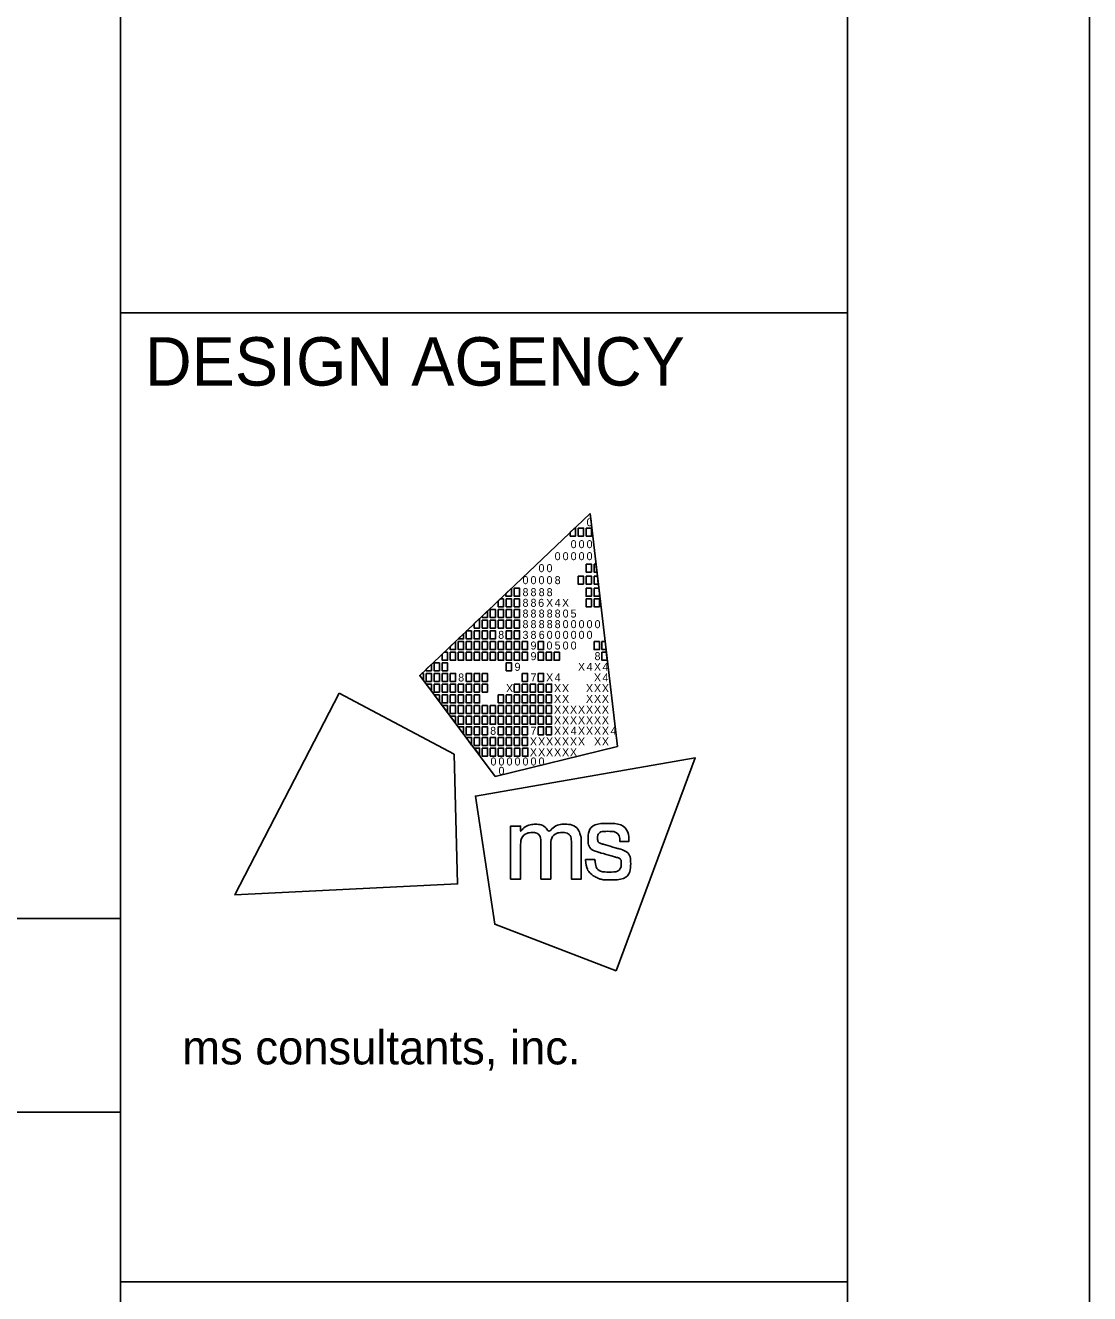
# Model space of a CAD drawing. Extents: x 0 to 59.1, y -2.4 to 22.
# Drawn here: x 31.803 to 34, y 2.976 to 5.594 of the extents above; entities that cross this region are included whole.
import ezdxf

# ---------------------------------------------------------------- set-up
doc = ezdxf.new("R2010")
doc.units = 0
for name, color, linetype in [('SH_Border', 7, 'Continuous'), ('SH_Cut_Line', 7, 'Continuous'), ('SH_Data', 7, 'Continuous'), ('SH_Text', 7, 'Continuous')]:
    doc.layers.add(name, color=color, linetype=linetype)

msp = doc.modelspace()

# ---------------------------------------------------------------- linework, layer by layer
at = {"layer": 'SH_Border'}
for p, q in [((32, 0.5), (32, 21.5)), ((32, 5), (33.5, 5)), ((32, 3), (33.5, 3))]:
    msp.add_line(p, q, dxfattribs=at)
msp.add_lwpolyline([(1.5, 21.5), (33.5, 21.5), (33.5, 0.5), (1.5, 0.5)], close=True, dxfattribs=at)
at = {"layer": 'SH_Cut_Line'}
msp.add_lwpolyline([(0, 0), (34, 0), (34, 22), (0, 22)], close=True, dxfattribs=at)
at = {"layer": 'SH_Data'}
for p, q in [((32.75, 4), (32.75, 4)), ((29.2, 3.75), (32, 3.75)), ((32, 3.75), (32, 0.5)), ((29.2, 3.35), (32, 3.35))]:
    msp.add_line(p, q, dxfattribs=at)
at = {"layer": 'SH_Text'}
for p, q in [((32.6175, 4.2519), (32.9688, 4.5861)), ((32.9688, 4.5861), (32.9688, 4.5861)), ((32.9688, 4.5861), (33.0253, 4.1052)), ((32.773, 4.043), (32.6175, 4.2519)), ((33.0253, 4.1052), (32.773, 4.043))]:
    msp.add_line(p, q, dxfattribs=at)
for points in [[(32.9279, 4.5472), (32.9369, 4.5558), (32.9389, 4.5558), (32.9389, 4.5393), (32.9279, 4.5393)], [(32.9444, 4.5558), (32.9554, 4.5558), (32.9554, 4.5393), (32.9444, 4.5393)], [(32.9609, 4.5558), (32.9719, 4.5558), (32.9719, 4.5393), (32.9609, 4.5393)], [(32.9606, 4.4815), (32.9716, 4.4815), (32.9716, 4.465), (32.9606, 4.465)], [(32.9771, 4.4815), (32.9811, 4.4815), (32.983, 4.465), (32.9771, 4.465)], [(32.9441, 4.4567), (32.9551, 4.4567), (32.9551, 4.4402), (32.9441, 4.4402)], [(32.9606, 4.4567), (32.9716, 4.4567), (32.9716, 4.4402), (32.9606, 4.4402)], [(32.9771, 4.4567), (32.984, 4.4567), (32.9859, 4.4402), (32.9771, 4.4402)], [(32.7953, 4.4211), (32.8064, 4.4316), (32.8064, 4.4154), (32.7953, 4.4154)], [(32.8123, 4.4319), (32.8233, 4.4319), (32.8233, 4.4154), (32.8123, 4.4154)], [(32.9606, 4.4319), (32.9716, 4.4319), (32.9716, 4.4154), (32.9606, 4.4154)], [(32.9771, 4.4319), (32.9869, 4.4319), (32.9881, 4.4218), (32.9881, 4.4154), (32.9771, 4.4154)], [(32.7958, 4.4099), (32.8068, 4.4099), (32.8068, 4.3934), (32.7958, 4.3934)], [(32.8123, 4.4099), (32.8233, 4.4099), (32.8233, 4.3934), (32.8123, 4.3934)], [(32.9606, 4.4099), (32.9716, 4.4099), (32.9716, 4.3934), (32.9606, 4.3934)], [(32.9771, 4.4099), (32.9881, 4.4099), (32.9881, 4.3934), (32.9771, 4.3934)], [(32.7627, 4.3879), (32.7737, 4.3879), (32.7737, 4.3714), (32.7627, 4.3714)], [(32.7793, 4.3879), (32.7903, 4.3879), (32.7903, 4.3714), (32.7793, 4.3714)], [(32.7958, 4.3879), (32.8068, 4.3879), (32.8068, 4.3714), (32.7958, 4.3714)], [(32.8123, 4.3879), (32.8233, 4.3879), (32.8233, 4.3714), (32.8123, 4.3714)], [(32.7462, 4.3659), (32.7572, 4.3659), (32.7572, 4.3494), (32.7462, 4.3494)], [(32.7627, 4.3659), (32.7737, 4.3659), (32.7737, 4.3494), (32.7627, 4.3494)], [(32.7793, 4.3659), (32.7903, 4.3659), (32.7903, 4.3494), (32.7793, 4.3494)], [(32.7958, 4.3659), (32.8068, 4.3659), (32.8068, 4.3494), (32.7958, 4.3494)], [(32.8123, 4.3659), (32.8233, 4.3659), (32.8233, 4.3494), (32.8123, 4.3494)], [(32.6967, 4.3218), (32.7077, 4.3218), (32.7077, 4.3053), (32.6967, 4.3053)], [(32.7132, 4.3218), (32.7242, 4.3218), (32.7242, 4.3053), (32.7132, 4.3053)], [(32.7297, 4.3439), (32.7407, 4.3439), (32.7407, 4.3273), (32.7297, 4.3273)], [(32.7297, 4.3218), (32.7407, 4.3218), (32.7407, 4.3053), (32.7297, 4.3053)], [(32.7462, 4.3439), (32.7572, 4.3439), (32.7572, 4.3273), (32.7462, 4.3273)], [(32.7462, 4.3218), (32.7572, 4.3218), (32.7572, 4.3053), (32.7462, 4.3053)], [(32.7627, 4.3439), (32.7737, 4.3439), (32.7737, 4.3273), (32.7627, 4.3273)], [(32.7627, 4.3218), (32.7737, 4.3218), (32.7737, 4.3053), (32.7627, 4.3053)], [(32.7793, 4.3218), (32.7903, 4.3218), (32.7903, 4.3053), (32.7793, 4.3053)], [(32.7958, 4.3439), (32.8068, 4.3439), (32.8068, 4.3273), (32.7958, 4.3273)], [(32.7958, 4.3218), (32.8068, 4.3218), (32.8068, 4.3053), (32.7958, 4.3053)], [(32.8123, 4.3439), (32.8233, 4.3439), (32.8233, 4.3273), (32.8123, 4.3273)], [(32.8123, 4.3218), (32.8233, 4.3218), (32.8233, 4.3053), (32.8123, 4.3053)], [(32.8288, 4.3218), (32.8398, 4.3218), (32.8398, 4.3053), (32.8288, 4.3053)], [(32.8618, 4.3218), (32.8728, 4.3218), (32.8728, 4.3053), (32.8618, 4.3053)], [(32.9771, 4.3218), (32.9881, 4.3218), (32.9881, 4.3053), (32.9771, 4.3053)], [(32.9935, 4.3218), (32.9998, 4.3218), (33.0018, 4.3053), (32.9935, 4.3053)], [(32.6802, 4.2998), (32.6912, 4.2998), (32.6912, 4.2833), (32.6802, 4.2833)], [(32.6967, 4.2998), (32.7077, 4.2998), (32.7077, 4.2833), (32.6967, 4.2833)], [(32.7132, 4.2998), (32.7242, 4.2998), (32.7242, 4.2833), (32.7132, 4.2833)], [(32.7297, 4.2998), (32.7407, 4.2998), (32.7407, 4.2833), (32.7297, 4.2833)], [(32.7462, 4.2998), (32.7572, 4.2998), (32.7572, 4.2833), (32.7462, 4.2833)], [(32.7627, 4.2998), (32.7737, 4.2998), (32.7737, 4.2833), (32.7627, 4.2833)], [(32.7793, 4.2998), (32.7903, 4.2998), (32.7903, 4.2833), (32.7793, 4.2833)], [(32.7958, 4.2998), (32.8068, 4.2998), (32.8068, 4.2833), (32.7958, 4.2833)], [(32.8123, 4.2998), (32.8233, 4.2998), (32.8233, 4.2833), (32.8123, 4.2833)], [(32.8288, 4.2998), (32.8398, 4.2998), (32.8398, 4.2833), (32.8288, 4.2833)], [(32.8618, 4.2998), (32.8728, 4.2998), (32.8728, 4.2833), (32.8618, 4.2833)], [(32.8783, 4.2998), (32.8893, 4.2998), (32.8893, 4.2833), (32.8783, 4.2833)], [(32.8947, 4.2998), (32.9057, 4.2998), (32.9057, 4.2833), (32.8947, 4.2833)], [(32.9935, 4.2998), (33.0024, 4.2998), (33.0044, 4.2833), (32.9935, 4.2833)], [(32.6471, 4.2778), (32.6581, 4.2778), (32.6581, 4.2613), (32.6471, 4.2613)], [(32.6637, 4.2778), (32.6747, 4.2778), (32.6747, 4.2613), (32.6637, 4.2613)], [(32.7958, 4.2778), (32.8068, 4.2778), (32.8068, 4.2613), (32.7958, 4.2613)], [(32.6306, 4.2558), (32.6416, 4.2558), (32.6416, 4.2393), (32.6306, 4.2393)], [(32.6471, 4.2558), (32.6581, 4.2558), (32.6581, 4.2393), (32.6471, 4.2393)], [(32.6637, 4.2558), (32.6747, 4.2558), (32.6747, 4.2393), (32.6637, 4.2393)], [(32.6802, 4.2558), (32.6912, 4.2558), (32.6912, 4.2393), (32.6802, 4.2393)], [(32.7132, 4.2558), (32.7242, 4.2558), (32.7242, 4.2393), (32.7132, 4.2393)], [(32.7297, 4.2558), (32.7407, 4.2558), (32.7407, 4.2393), (32.7297, 4.2393)], [(32.7462, 4.2558), (32.7572, 4.2558), (32.7572, 4.2393), (32.7462, 4.2393)], [(32.8288, 4.2558), (32.8398, 4.2558), (32.8398, 4.2393), (32.8288, 4.2393)], [(32.8618, 4.2558), (32.8728, 4.2558), (32.8728, 4.2393), (32.8618, 4.2393)], [(32.6306, 4.2338), (32.6416, 4.2338), (32.6416, 4.22)], [(32.6471, 4.2338), (32.6581, 4.2338), (32.6581, 4.2173), (32.6471, 4.2173)], [(32.6637, 4.2338), (32.6747, 4.2338), (32.6747, 4.2173), (32.6637, 4.2173)], [(32.6802, 4.2338), (32.6912, 4.2338), (32.6912, 4.2173), (32.6802, 4.2173)], [(32.6967, 4.2338), (32.7077, 4.2338), (32.7077, 4.2173), (32.6967, 4.2173)], [(32.7132, 4.2338), (32.7242, 4.2338), (32.7242, 4.2173), (32.7132, 4.2173)], [(32.7297, 4.2338), (32.7407, 4.2338), (32.7407, 4.2173), (32.7297, 4.2173)], [(32.7462, 4.2338), (32.7572, 4.2338), (32.7572, 4.2173), (32.7462, 4.2173)], [(32.8123, 4.2338), (32.8233, 4.2338), (32.8233, 4.2173), (32.8123, 4.2173)], [(32.8288, 4.2338), (32.8398, 4.2338), (32.8398, 4.2173), (32.8288, 4.2173)], [(32.8453, 4.2338), (32.8563, 4.2338), (32.8563, 4.2173), (32.8453, 4.2173)], [(32.8618, 4.2338), (32.8728, 4.2338), (32.8728, 4.2173), (32.8618, 4.2173)], [(32.8783, 4.2338), (32.8893, 4.2338), (32.8893, 4.2173), (32.8783, 4.2173)], [(32.6471, 4.2117), (32.6581, 4.2117), (32.6581, 4.198)], [(32.6637, 4.2117), (32.6747, 4.2117), (32.6747, 4.1952), (32.6637, 4.1952)], [(32.6637, 4.1897), (32.6747, 4.1897), (32.6747, 4.176)], [(32.6747, 4.1897), (32.6747, 4.1897), (32.6747, 4.1897)], [(32.6802, 4.2117), (32.6912, 4.2117), (32.6912, 4.1952), (32.6802, 4.1952)], [(32.6802, 4.1897), (32.6912, 4.1897), (32.6912, 4.1732), (32.6802, 4.1732)], [(32.6967, 4.2117), (32.7077, 4.2117), (32.7077, 4.1952), (32.6967, 4.1952)], [(32.6967, 4.1897), (32.7077, 4.1897), (32.7077, 4.1732), (32.6967, 4.1732)], [(32.7132, 4.2117), (32.7242, 4.2117), (32.7242, 4.1952), (32.7132, 4.1952)], [(32.7132, 4.1897), (32.7242, 4.1897), (32.7242, 4.1732), (32.7132, 4.1732)], [(32.7297, 4.2117), (32.7407, 4.2117), (32.7407, 4.1952), (32.7297, 4.1952)], [(32.7297, 4.1897), (32.7407, 4.1897), (32.7407, 4.1732), (32.7297, 4.1732)], [(32.7462, 4.1897), (32.7572, 4.1897), (32.7572, 4.1732), (32.7462, 4.1732)], [(32.7627, 4.1897), (32.7737, 4.1897), (32.7737, 4.1732), (32.7627, 4.1732)], [(32.7793, 4.2117), (32.7903, 4.2117), (32.7903, 4.1952), (32.7793, 4.1952)], [(32.7793, 4.1897), (32.7903, 4.1897), (32.7903, 4.1732), (32.7793, 4.1732)], [(32.7958, 4.2117), (32.8068, 4.2117), (32.8068, 4.1952), (32.7958, 4.1952)], [(32.7958, 4.1897), (32.8068, 4.1897), (32.8068, 4.1732), (32.7958, 4.1732)], [(32.8123, 4.2117), (32.8233, 4.2117), (32.8233, 4.1952), (32.8123, 4.1952)], [(32.8123, 4.1897), (32.8233, 4.1897), (32.8233, 4.1732), (32.8123, 4.1732)], [(32.8288, 4.2117), (32.8398, 4.2117), (32.8398, 4.1952), (32.8288, 4.1952)], [(32.8288, 4.1897), (32.8398, 4.1897), (32.8398, 4.1732), (32.8288, 4.1732)], [(32.8453, 4.2117), (32.8563, 4.2117), (32.8563, 4.1952), (32.8453, 4.1952)], [(32.8453, 4.1897), (32.8563, 4.1897), (32.8563, 4.1732), (32.8453, 4.1732)], [(32.8618, 4.2117), (32.8728, 4.2117), (32.8728, 4.1952), (32.8618, 4.1952)], [(32.8618, 4.1897), (32.8728, 4.1897), (32.8728, 4.1732), (32.8618, 4.1732)], [(32.8783, 4.2117), (32.8893, 4.2117), (32.8893, 4.1952), (32.8783, 4.1952)], [(32.8783, 4.1897), (32.8893, 4.1897), (32.8893, 4.1732), (32.8783, 4.1732)], [(32.6802, 4.1677), (32.6912, 4.1677), (32.6912, 4.154)], [(32.6967, 4.1677), (32.7077, 4.1677), (32.7077, 4.1512), (32.6967, 4.1512)], [(32.7132, 4.1677), (32.7242, 4.1677), (32.7242, 4.1512), (32.7132, 4.1512)], [(32.7297, 4.1677), (32.7407, 4.1677), (32.7407, 4.1512), (32.7297, 4.1512)], [(32.7462, 4.1677), (32.7572, 4.1677), (32.7572, 4.1512), (32.7462, 4.1512)], [(32.7627, 4.1677), (32.7737, 4.1677), (32.7737, 4.1512), (32.7627, 4.1512)], [(32.7793, 4.1677), (32.7903, 4.1677), (32.7903, 4.1512), (32.7793, 4.1512)], [(32.7958, 4.1677), (32.8068, 4.1677), (32.8068, 4.1512), (32.7958, 4.1512)], [(32.8123, 4.1677), (32.8233, 4.1677), (32.8233, 4.1512), (32.8123, 4.1512)], [(32.8288, 4.1677), (32.8398, 4.1677), (32.8398, 4.1512), (32.8288, 4.1512)], [(32.8453, 4.1677), (32.8563, 4.1677), (32.8563, 4.1512), (32.8453, 4.1512)], [(32.8618, 4.1677), (32.8728, 4.1677), (32.8728, 4.1512), (32.8618, 4.1512)], [(32.8783, 4.1677), (32.8893, 4.1677), (32.8893, 4.1512), (32.8783, 4.1512)], [(32.7077, 4.1305), (32.6965, 4.1457), (32.7077, 4.1457)], [(32.7132, 4.1457), (32.7242, 4.1457), (32.7242, 4.1292), (32.7132, 4.1292)], [(32.7297, 4.1457), (32.7407, 4.1457), (32.7407, 4.1292), (32.7297, 4.1292)], [(32.7462, 4.1457), (32.7572, 4.1457), (32.7572, 4.1292), (32.7462, 4.1292)], [(32.7793, 4.1457), (32.7903, 4.1457), (32.7903, 4.1292), (32.7793, 4.1292)], [(32.7958, 4.1457), (32.8068, 4.1457), (32.8068, 4.1292), (32.7958, 4.1292)], [(32.8123, 4.1457), (32.8233, 4.1457), (32.8233, 4.1292), (32.8123, 4.1292)], [(32.8288, 4.1457), (32.8398, 4.1457), (32.8398, 4.1292), (32.8288, 4.1292)], [(32.8618, 4.1457), (32.8728, 4.1457), (32.8728, 4.1292), (32.8618, 4.1292)], [(32.8783, 4.1457), (32.8893, 4.1457), (32.8893, 4.1292), (32.8783, 4.1292)], [(32.724, 4.1082), (32.7132, 4.1237), (32.7242, 4.1237)], [(32.7297, 4.1237), (32.7407, 4.1237), (32.7407, 4.1072), (32.7297, 4.1072)], [(32.7462, 4.1237), (32.7572, 4.1237), (32.7572, 4.1072), (32.7462, 4.1072)], [(32.7627, 4.1237), (32.7737, 4.1237), (32.7737, 4.1072), (32.7627, 4.1072)], [(32.7793, 4.1237), (32.7903, 4.1237), (32.7903, 4.1072), (32.7793, 4.1072)], [(32.7958, 4.1237), (32.8068, 4.1237), (32.8068, 4.1072), (32.7958, 4.1072)], [(32.8123, 4.1237), (32.8233, 4.1237), (32.8233, 4.1072), (32.8123, 4.1072)], [(32.8288, 4.1237), (32.8398, 4.1237), (32.8398, 4.1072), (32.8288, 4.1072)], [(32.7302, 4.1017), (32.7407, 4.1017), (32.7408, 4.0875)], [(32.7463, 4.1017), (32.7573, 4.1017), (32.7573, 4.0852), (32.7463, 4.0852)], [(32.763, 4.1017), (32.774, 4.1017), (32.774, 4.0852), (32.763, 4.0852)], [(32.7794, 4.1017), (32.7904, 4.1017), (32.7904, 4.0852), (32.7794, 4.0852)], [(32.796, 4.1017), (32.807, 4.1017), (32.807, 4.0852), (32.796, 4.0852)], [(32.8129, 4.1017), (32.8239, 4.1017), (32.8239, 4.0851), (32.8129, 4.0851)], [(32.8296, 4.1017), (32.8406, 4.1017), (32.8406, 4.0851), (32.8296, 4.0851)]]:
    msp.add_lwpolyline(points, close=True, dxfattribs=at)
for points in [[(32.7903, 4.4099), (32.7836, 4.4099), (32.7793, 4.4058), (32.7793, 4.3934), (32.7903, 4.3934), (32.7903, 4.4099)], [(32.7572, 4.3849), (32.7462, 4.3744), (32.7462, 4.3714), (32.7572, 4.3714), (32.7572, 4.3849)], [(32.7407, 4.3691), (32.7297, 4.3587), (32.7297, 4.3494), (32.7407, 4.3494), (32.7407, 4.3691)], [(32.6912, 4.322), (32.6802, 4.3115), (32.6802, 4.3053), (32.6912, 4.3053), (32.6912, 4.322)], [(32.7077, 4.3377), (32.6968, 4.3273), (32.7077, 4.3273), (32.7077, 4.3377)], [(32.7242, 4.3439), (32.7141, 4.3439), (32.7132, 4.343), (32.7132, 4.3273), (32.7242, 4.3273), (32.7242, 4.3439)], [(32.6747, 4.2998), (32.6679, 4.2998), (32.6637, 4.2958), (32.6637, 4.2833), (32.6747, 4.2833), (32.6747, 4.2998)], [(32.6416, 4.2749), (32.6306, 4.2644), (32.6306, 4.2613), (32.6416, 4.2613), (32.6416, 4.2749)], [(32.6251, 4.2558), (32.6216, 4.2558), (32.6175, 4.2519), (32.6251, 4.2417), (32.6251, 4.2558)], [(32.4512, 4.2149), (32.2359, 3.7988), (32.6956, 3.8215), (32.6884, 4.0892), (32.4512, 4.2149)], [(33.0229, 3.6422), (33.1859, 4.0814), (32.7324, 4.0029), (32.7722, 3.7381), (33.0229, 3.6422)]]:
    msp.add_lwpolyline(points, dxfattribs=at)
for points in [[(32.8048, 3.8315), (32.8048, 3.8315), (32.8048, 3.9409), (32.8048, 3.9409), (32.8048, 3.9409), (32.8255, 3.9409), (32.8255, 3.9409), (32.8255, 3.9409), (32.8255, 3.9297), (32.8255, 3.9297), (32.8346, 3.9399), (32.8457, 3.9445), (32.8555, 3.9445), (32.8688, 3.9445), (32.8791, 3.9372), (32.8837, 3.9266), (32.8915, 3.9381), (32.905, 3.9446), (32.9166, 3.9446), (32.9325, 3.9446), (32.9451, 3.935), (32.9494, 3.9213), (32.9494, 3.9212), (32.9494, 3.9212), (32.9494, 3.9212), (32.9501, 3.919), (32.9506, 3.9172), (32.9506, 3.9071), (32.9506, 3.9071), (32.9506, 3.8314), (32.9506, 3.8314), (32.9506, 3.8314), (32.9303, 3.8314), (32.9303, 3.8314), (32.9303, 3.8314), (32.9303, 3.9048), (32.9303, 3.9048), (32.9303, 3.9201), (32.9219, 3.9274), (32.911, 3.9274), (32.8995, 3.9274), (32.8879, 3.9171), (32.8879, 3.9001), (32.8879, 3.9001), (32.8879, 3.8315), (32.8879, 3.8315), (32.8879, 3.8315), (32.8674, 3.8315), (32.8674, 3.8315), (32.8674, 3.8315), (32.8674, 3.9059), (32.8674, 3.9059), (32.8674, 3.9203), (32.8588, 3.9274), (32.8496, 3.9274), (32.8384, 3.9274), (32.8254, 3.917), (32.8254, 3.8962), (32.8254, 3.8962), (32.8254, 3.8315), (32.8254, 3.8315), (32.8254, 3.8315), (32.8048, 3.8315), (32.8048, 3.8315)], [(32.9595, 3.8709), (32.9595, 3.8709), (32.9595, 3.8717), (32.9595, 3.8717), (32.9595, 3.8717), (32.9603, 3.8717), (32.9603, 3.8717), (32.9603, 3.8717), (32.9783, 3.8717), (32.9783, 3.8717), (32.9783, 3.8717), (32.9789, 3.8717), (32.9789, 3.8717), (32.9789, 3.8717), (32.979, 3.871), (32.979, 3.871), (32.9803, 3.8554), (32.9887, 3.846), (33.009, 3.846), (33.0273, 3.846), (33.0333, 3.8554), (33.0333, 3.8631), (33.0333, 3.8732), (33.0256, 3.8758), (33.0175, 3.878), (33.0175, 3.878), (32.987, 3.8867), (32.987, 3.8867), (32.972, 3.8909), (32.9648, 3.9019), (32.9648, 3.9142), (32.9648, 3.9303), (32.9768, 3.9462), (33.0052, 3.9462), (33.0348, 3.9462), (33.0489, 3.9285), (33.0489, 3.9095), (33.0489, 3.9095), (33.0489, 3.9087), (33.0489, 3.9087), (33.0489, 3.9087), (33.0482, 3.9087), (33.0482, 3.9087), (33.0482, 3.9087), (33.0312, 3.9087), (33.0312, 3.9087), (33.0312, 3.9087), (33.0305, 3.9087), (33.0305, 3.9087), (33.0305, 3.9087), (33.0305, 3.9094), (33.0305, 3.9094), (33.0301, 3.9208), (33.0226, 3.93), (33.0056, 3.93), (32.9891, 3.93), (32.9843, 3.9218), (32.9843, 3.9157), (32.9843, 3.9108), (32.9869, 3.9059), (32.9959, 3.9033), (32.9959, 3.9033), (33.0255, 3.8948), (33.0255, 3.8948), (33.0462, 3.8889), (33.0527, 3.8777), (33.0527, 3.8639), (33.0527, 3.8462), (33.041, 3.8298), (33.0087, 3.8298), (32.9952, 3.8298), (32.9877, 3.8321), (32.9823, 3.8348), (32.969, 3.8414), (32.9609, 3.8536), (32.9595, 3.8709)]]:
    msp.add_open_spline(points, degree=3, dxfattribs=at)

# ---------------------------------------------------------------- texts
at = {"layer": 'SH_Border'}
msp.add_text('ms consultants, inc.', height=0.07, rotation=360, dxfattribs=at).set_placement((32.1273, 3.4489))
at = {"layer": 'SH_Data'}
msp.add_text('DESIGN AGENCY', height=0.1, dxfattribs=at).set_placement((32.05, 4.85))
at = {"layer": 'SH_Text'}
for s, p in [('0', (32.9617, 4.5597)), ('0', (32.9288, 4.5145)), ('0', (32.9452, 4.5145)), ('0', (32.9617, 4.5145)), ('0', (32.8958, 4.4897)), ('0', (32.9123, 4.4897)), ('0', (32.9288, 4.4897)), ('0', (32.9452, 4.4897)), ('0', (32.9617, 4.4897)), ('0', (32.8625, 4.465)), ('0', (32.879, 4.465)), ('0', (32.8295, 4.4402)), ('0', (32.846, 4.4402)), ('0', (32.8625, 4.4402)), ('0', (32.879, 4.4402)), ('8', (32.8958, 4.4402)), ('8', (32.8295, 4.4154)), ('8', (32.846, 4.4154)), ('8', (32.8628, 4.4154)), ('8', (32.8793, 4.4154)), ('8', (32.8295, 4.3934)), ('8', (32.846, 4.3934)), ('6', (32.8618, 4.3934)), ('X', (32.8781, 4.3934)), ('4', (32.8958, 4.3934)), ('X', (32.911, 4.3934)), ('8', (32.8295, 4.3713)), ('8', (32.846, 4.3713)), ('8', (32.8628, 4.3713)), ('8', (32.8794, 4.3713)), ('8', (32.8958, 4.3713)), ('0', (32.9123, 4.3713)), ('5', (32.9287, 4.3713)), ('8', (32.8295, 4.3494)), ('8', (32.846, 4.3494)), ('8', (32.8628, 4.3494)), ('8', (32.8794, 4.3494)), ('8', (32.8958, 4.3494)), ('0', (32.9123, 4.3494)), ('0', (32.9288, 4.3494)), ('0', (32.9452, 4.3494)), ('0', (32.9617, 4.3494)), ('0', (32.9782, 4.3494)), ('8', (32.7793, 4.3273)), ('3', (32.8295, 4.3273)), ('8', (32.846, 4.3273)), ('9', (32.846, 4.3053)), ('6', (32.8629, 4.3273)), ('0', (32.879, 4.3053)), ('0', (32.8793, 4.3273)), ('5', (32.8957, 4.3053)), ('0', (32.8958, 4.3273)), ('0', (32.9123, 4.3273)), ('0', (32.9123, 4.3053)), ('0', (32.9288, 4.3273)), ('0', (32.9288, 4.3053)), ('0', (32.9452, 4.3273)), ('0', (32.9617, 4.3273)), ('9', (32.846, 4.2833)), ('8', (32.9781, 4.2833)), ('9', (32.813, 4.2613)), ('X', (32.9439, 4.2613)), ('4', (32.9617, 4.2613)), ('X', (32.9769, 4.2613)), ('4', (32.9946, 4.2613)), ('8', (32.6967, 4.2393)), ('7', (32.846, 4.2393)), ('X', (32.8781, 4.2393)), ('4', (32.8958, 4.2393)), ('X', (32.9769, 4.2393)), ('4', (32.9946, 4.2393)), ('X', (32.7955, 4.2173)), ('X', (32.8945, 4.2173)), ('X', (32.911, 4.2173)), ('X', (32.9604, 4.2173)), ('X', (32.9769, 4.2173)), ('X', (32.9933, 4.2173)), ('X', (32.8945, 4.1952)), ('X', (32.8945, 4.1732)), ('X', (32.911, 4.1952)), ('X', (32.911, 4.1732)), ('X', (32.9274, 4.1732)), ('X', (32.9439, 4.1732)), ('X', (32.9604, 4.1952)), ('X', (32.9604, 4.1732)), ('X', (32.9769, 4.1952)), ('X', (32.9769, 4.1732)), ('X', (32.9933, 4.1952)), ('X', (32.9933, 4.1732)), ('X', (32.8945, 4.1512)), ('X', (32.911, 4.1512)), ('X', (32.9274, 4.1512)), ('X', (32.9439, 4.1512)), ('X', (32.9604, 4.1512)), ('X', (32.9769, 4.1512)), ('X', (32.9933, 4.1512)), ('8', (32.7627, 4.1292)), ('7', (32.846, 4.1292)), ('X', (32.8945, 4.1292)), ('X', (32.911, 4.1292)), ('4', (32.9288, 4.1292)), ('X', (32.9439, 4.1292)), ('X', (32.9604, 4.1292)), ('X', (32.9769, 4.1292)), ('X', (32.9933, 4.1292)), ('4', (33.0111, 4.1292)), ('X', (32.8447, 4.1072)), ('X', (32.8616, 4.1072)), ('X', (32.878, 4.1072)), ('X', (32.8945, 4.1072)), ('X', (32.911, 4.1072)), ('X', (32.9274, 4.1072)), ('X', (32.9439, 4.1072)), ('X', (32.9771, 4.1072)), ('X', (32.9933, 4.1072)), ('X', (32.8447, 4.0851)), ('X', (32.8616, 4.0851)), ('X', (32.878, 4.0851)), ('X', (32.8945, 4.0851)), ('X', (32.911, 4.0851)), ('X', (32.9274, 4.0851)), ('0', (32.7634, 4.0659)), ('0', (32.7799, 4.0659)), ('0', (32.7799, 4.0467)), ('0', (32.7965, 4.0659)), ('0', (32.813, 4.0659)), ('0', (32.8295, 4.0659)), ('0', (32.846, 4.0659)), ('0', (32.8625, 4.0659))]:
    msp.add_text(s, height=0.0165, rotation=360, dxfattribs=at).set_placement(p)

doc.saveas('drawing.dxf')
